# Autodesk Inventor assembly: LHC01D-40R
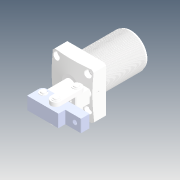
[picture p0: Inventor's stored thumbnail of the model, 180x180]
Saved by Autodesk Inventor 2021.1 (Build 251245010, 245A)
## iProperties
Created: 2019-04
Part Number: LHC01D-40R
Description: STEP AP214
Document SubType Name: Assembly
Designer: user
Title: LHC01D-40R.STEP
Revision Number: ÈÎºÎ
Sending System: SolidWorks 2016
Preprocessor: SwSTEP 2.0
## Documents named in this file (13)
- D:\Vault_2016\Projekty\Clamptek\Hydraulic\LHC01D\Inventor\LHC01D-40R\LHC01D-40R.iam
- D:\Vault_2016\Projekty\Clamptek\Hydraulic\LHC01D\Inventor\LHC01D-40R\040R±¾Ìå.ipt
- D:\Vault_2016\Projekty\Clamptek\Hydraulic\LHC01D\Inventor\LHC01D-40R\4_40.ipt
- D:\Vault_2016\Projekty\Clamptek\Hydraulic\LHC01D\Inventor\LHC01D-40R\6_4.ipt
- D:\Vault_2016\Projekty\Clamptek\Hydraulic\LHC01D\Inventor\LHC01D-40R\7_4.ipt
- D:\Vault_2016\Projekty\Clamptek\Hydraulic\LHC01D\Inventor\LHC01D-40R\8_4.ipt
- D:\Vault_2016\Projekty\Clamptek\Hydraulic\LHC01D\Inventor\LHC01D-40R\9_4.ipt
- D:\Vault_2016\Projekty\Clamptek\Hydraulic\LHC01D\Inventor\LHC01D-40R\10_4.ipt
- D:\Vault_2016\Projekty\Clamptek\Hydraulic\LHC01D\Inventor\LHC01D-40R\11_4.ipt
- D:\Vault_2016\Projekty\Clamptek\Hydraulic\LHC01D\Inventor\LHC01D-40R\12_4.ipt
- D:\Vault_2016\Projekty\Clamptek\Hydraulic\LHC01D\Inventor\LHC01D-40R\5_4.ipt
- D:\Vault_2016\Projekty\Clamptek\Hydraulic\LHC01D\Inventor\LHC01D-40R\¶ÂÍ·_9.ipt
- D:\Vault_2016\Projekty\Clamptek\Hydraulic\LHC01D\Inventor\LHC01D-40R\LHC01D40»îÈû¸Ë.ipt
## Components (27 placed, 27 different names)
1. 040R±¾Ìå_1
2. 4_40_2
3. 6_4_3
4. 7_4_4
5. 7_4_5
6. 8_4_6
7. 9_4_7
8. 9_4_8
9. 9_4_9
10. 9_4_10
11. 9_4_11
12. 9_4_12
13. 10_4_13
14. 10_4_14
15. 10_4_15
16. 10_4_16
17. 10_4_17
18. 11_4_18
19. 11_4_19
20. 12_4_20
21. 12_4_21
22. 5_4_22
23. 5_4_23
24. 10_4_24
25. ¶ÂÍ·_9_25
26. ¶ÂÍ·_9_26
27. LHC01D40»îÈû¸Ë_27
